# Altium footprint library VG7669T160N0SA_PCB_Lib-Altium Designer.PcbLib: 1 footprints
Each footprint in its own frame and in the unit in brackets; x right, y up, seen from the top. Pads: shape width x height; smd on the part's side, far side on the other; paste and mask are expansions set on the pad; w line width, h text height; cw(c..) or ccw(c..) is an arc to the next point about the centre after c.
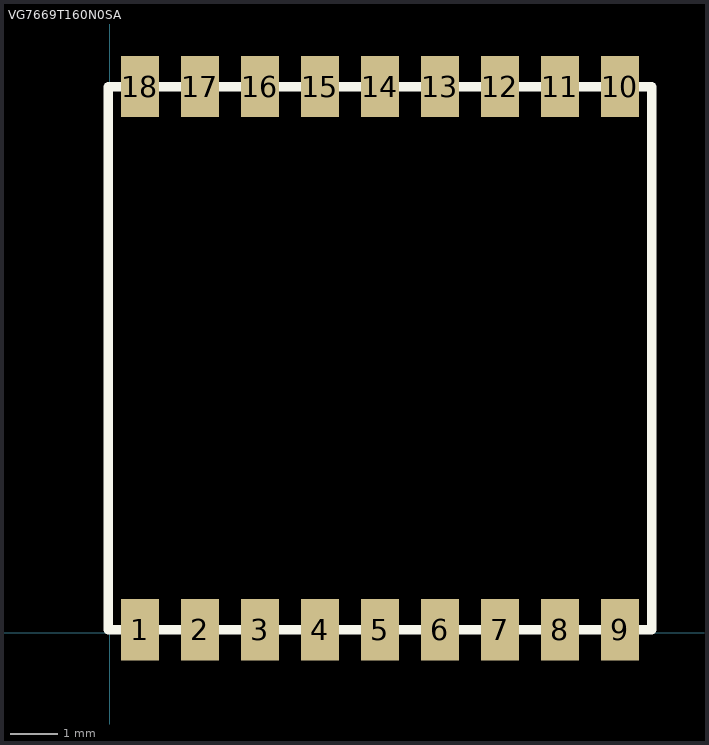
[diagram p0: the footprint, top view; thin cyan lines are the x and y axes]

## VG7669T160N0SA [mm]
pads (19):
  round 1 on Top Overlay: 1(-0.635,-0.762)
  rect 0.8x1.3 smd: 1(0.635,0.057) 2(1.905,0.057) 3(3.175,0.057) 4(4.445,0.057) 5(5.715,0.057) 6(6.985,0.057) 7(8.255,0.057) 8(9.525,0.057) 9(10.795,0.057) 10(10.795,11.557) 11(9.525,11.557) 12(8.255,11.557) 13(6.985,11.557) 14(5.715,11.557) 15(4.445,11.557) 16(3.175,11.557) 17(1.905,11.557) 18(0.635,11.557)
Top Overlay:
  lines w0.2: -0.035,0.057 -0.035,11.557 11.465,11.557 11.465,0.057 -0.035,0.057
